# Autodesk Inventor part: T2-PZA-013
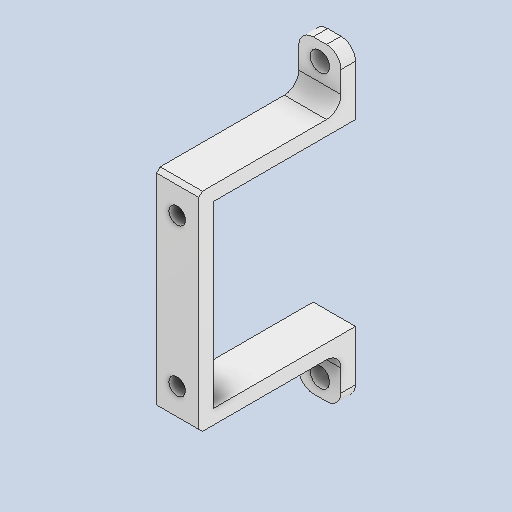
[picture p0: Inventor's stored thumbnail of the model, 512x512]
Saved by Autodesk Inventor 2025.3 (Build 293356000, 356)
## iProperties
Created: 2026-10
Part Number: T2-PZA-013
Material: Genérico
Description: Brida de montaje del servomotor
Document SubType Name: Modeling
Designer: Luis MuÃ±oz
Density: 1 g/cm^3
Appearance: Valor por defecto
Project: TESIS 2 - Plataforma mecatrÃ³nica preventiva desacoplada
Sending System: ONSHAPE BY PTC INC, 1.194
Preprocessor: ST-DEVELOPER v20
Material_Fabricacion: PLA
Title: Brida de montaje del servomotor
Revision Number: 00
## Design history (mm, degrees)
feature "Motor_Flange"
node "Sólido1"
